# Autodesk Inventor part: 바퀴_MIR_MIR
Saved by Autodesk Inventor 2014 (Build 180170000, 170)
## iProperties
Created: 2015-05
Part Number: 바퀴_MIR_MIR
Material: 일반
Vendor: CBT Solutions
Document SubType Name: 모델링
Designer: Administrator
Appearance: 기본값
Company: 한국ATC센터
Author: KYOUNG IL JANG
Comments: 파생
d0: 1.000 ul
d0_1: 1.000 ul
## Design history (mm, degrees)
derived "바퀴_MIR.ipt"
feature "솔리드1::바퀴_MIR.ipt"
tag "피쳐 태그1"
node "솔리드1"
other parameters: "d0" = 1, "d0_1" = 1
